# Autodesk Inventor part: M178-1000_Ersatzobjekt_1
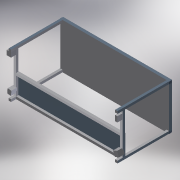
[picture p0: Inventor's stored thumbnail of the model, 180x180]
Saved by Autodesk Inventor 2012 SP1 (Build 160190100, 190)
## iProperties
Created: 2012-04
Part Number: M178-1000_Ersatzobjekt_1
Material: 1.0038 St 37-2K
Document SubType Name: Modeling
Designer: jwagner
Density: 7.85 g/cm^3
RuleStatus: InUse
AfterMaterialChange0: Fx.Material.Update
AfterAnyiPropertyChange0: iProp.Update
AfterAnyiPropertyChange1: Fx.Material.Update
Author: jwagner
Revision Number: A
ABMESSUNG_HZ: 100x100x10
BESCHREIBUNG: <freier Text>
EV_KENNUNG: <keine>
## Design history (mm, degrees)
derived "M178-1000.iam"
node "Volumenkörper3"
sketch "M178-1001.ipt:1"
sketch "M178-1100.iam:1"
sketch "M178-1000-Phantom01.iam:1"
sketch "M178-1000-Phantom01.iam:11"
sketch "M178-1000-Phantom01.iam:3"
sketch "M178-1000-Phantom01.iam:4"
sketch "M178-1000-Phantom01.iam:5"
sketch "M178-1000-Phantom01.iam:6"
sketch "M178-1000-Phantom01.iam:7"
sketch "M178-1000-Phantom01.iam:8"
sketch "M178-1000-Phantom01.iam:12"
sketch "M178-1000-Phantom01.iam:10"
sketch "M178-1000_Leg_Phantom.iam:1"
sketch "M178-1000_Leg_Phantom.iam:2"
sketch "M178-1000_Leg_Phantom.iam:3"
sketch "M178-1000_Leg_Phantom.iam:4"
node "M178-1005.ipt:1"
node "M178-1005.ipt:2"
sketch "20-004.iam:1"
sketch "20-004.iam:2"
sketch "20-004.iam:3"
sketch "20-004.iam:4"
sketch "M178-100_Cross_Phantom.iam:1"
sketch "M178-100_Cross_Phantom.iam:2"
sketch "21-092 Caster Phantom.iam:1"
sketch "21-091 Caster Phantom.iam:1"
sketch "21-092 Caster Phantom.iam:2"
sketch "21-091 Caster Phantom.iam:2"
sketch "M178-1007.ipt:1"
sketch "M178-1000-Phantom01.iam:13"
sketch "M178-1000-Phantom01.iam:15"
sketch "M178-1000-Phantom01.iam:16"
sketch "M178-1000-Phantom01.iam:17"
sketch "M178-1000-Phantom01.iam:14"
sketch "M178-1000-Phantom01.iam:18"
sketch "M178-1000-Phantom01.iam:19"
sketch "M178-1000-Phantom01.iam:20"
sketch "M178-1000-Phantom01.iam:21"
sketch "M178-1000-Phantom01.iam:22"
sketch "18-813.ipt:1"
sketch "18-813.ipt:2"
sketch "18-813.ipt:3"
sketch "18-813.ipt:4"
node "M178-1000.iam_Körper"
other parameters: "Length" = 1828.8, "Length_1" = 1828.8, "Length_2" = 682, "Length_3" = 682, "Length_4" = 1748.8, "Length_5" = 812.8, "Length_6" = 812.8, "Length_7" = 812.8, "Length_8" = 812.8, "Length_9" = 1748.8, "Length_10" = 1748.8, "Length_11" = 682, "Length_12" = 682
